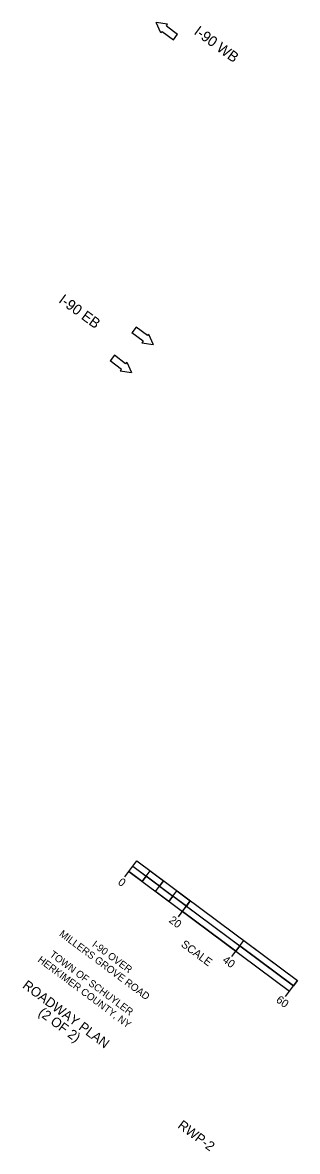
# Model space of a CAD drawing. Extents: x 337412 to 338044, y 1540627 to 1541298.
# Drawn here: x 337776.6 to 337858.9, y 1540627.3 to 1540965.9 of the extents above; entities that cross this region are included whole.
import ezdxf

# ---------------------------------------------------------------- set-up
doc = ezdxf.new("R2010")
doc.units = 0
for name, color, linetype in [('Default', 7, 'Continuous'), ('NSB_P', 7, 'Continuous'), ('NSB_P_T', 7, 'Continuous'), ('O_Details_Dimensions_Notes_P', 7, 'Continuous'), ('O_Details_Object Line 1_P', 7, 'Continuous')]:
    doc.layers.add(name, color=color, linetype=linetype)

msp = doc.modelspace()

# ---------------------------------------------------------------- linework, layer by layer
at = {"layer": 'NSB_P'}
for p, q in [((337807.22, 1540709.63), (337810.8, 1540714.45)), ((337810.8, 1540714.45), (337858.92, 1540678.61)), ((337808.41, 1540711.24), (337856.53, 1540675.4)), ((337809.6, 1540712.84), (337857.73, 1540677.01)), ((337812.42, 1540708.25), (337813.61, 1540709.85)), ((337816.43, 1540705.26), (337818.82, 1540708.47)), ((337820.44, 1540702.28), (337822.83, 1540705.49)), ((337823.26, 1540697.69), (337826.84, 1540702.5)), ((337839.3, 1540685.74), (337842.88, 1540690.55)), ((337855.34, 1540673.8), (337858.92, 1540678.61))]:
    msp.add_line(p, q, dxfattribs=at)
for points in [[(337809.6, 1540712.84), (337813.61, 1540709.85), (337812.42, 1540708.25), (337808.41, 1540711.24)], [(337814.81, 1540711.46), (337818.82, 1540708.47), (337817.62, 1540706.87), (337813.61, 1540709.85)], [(337817.62, 1540706.87), (337821.63, 1540703.88), (337820.44, 1540702.28), (337816.43, 1540705.26)], [(337822.83, 1540705.49), (337826.84, 1540702.5), (337825.65, 1540700.9), (337821.63, 1540703.88)], [(337825.65, 1540700.9), (337841.69, 1540688.95), (337840.49, 1540687.35), (337824.45, 1540699.29)], [(337842.88, 1540690.55), (337858.92, 1540678.61), (337857.73, 1540677.01), (337841.69, 1540688.95)]]:
    msp.add_lwpolyline(points, close=True, dxfattribs=at)
at = {"layer": 'O_Details_Object Line 1_P'}
for p, q in [((337820.03, 1540965.41), (337816.64, 1540965.89)), ((337818.04, 1540962.77), (337816.64, 1540965.89)), ((337819.66, 1540964.93), (337820.03, 1540965.41)), ((337819.66, 1540964.93), (337823.02, 1540962.4)), ((337818.04, 1540962.77), (337818.4, 1540963.25)), ((337818.4, 1540963.25), (337821.76, 1540960.72)), ((337821.76, 1540960.72), (337823.02, 1540962.4)), ((337810.62, 1540874.52), (337809.36, 1540872.84)), ((337813.98, 1540871.99), (337810.62, 1540874.52)), ((337812.72, 1540870.32), (337809.36, 1540872.84)), ((337812.72, 1540870.32), (337812.36, 1540869.84)), ((337812.36, 1540869.84), (337815.75, 1540869.35)), ((337814.34, 1540872.47), (337813.98, 1540871.99)), ((337814.34, 1540872.47), (337815.75, 1540869.35)), ((337804.08, 1540866.09), (337802.82, 1540864.41)), ((337806.18, 1540861.88), (337802.82, 1540864.41)), ((337807.44, 1540863.56), (337804.08, 1540866.09)), ((337807.8, 1540864.04), (337807.44, 1540863.56)), ((337807.8, 1540864.04), (337809.2, 1540860.92)), ((337806.18, 1540861.88), (337805.82, 1540861.4)), ((337805.82, 1540861.4), (337809.2, 1540860.92))]:
    msp.add_line(p, q, dxfattribs=at)

# ---------------------------------------------------------------- texts
at = {"layer": 'Default'}
for s, height, p in [('MILLERS GROVE ROAD', 2.16, (337787.39, 1540692.14)), ('I-90 OVER', 2.16, (337797.21, 1540688.99)), ('TOWN OF SCHUYLER', 2.16, (337784.52, 1540685.96)), ('HERKIMER COUNTY, NY', 2.16, (337780.93, 1540684.38)), ('ROADWAY PLAN', 2.88, (337776.33, 1540676.59)), ('(2 OF 2)', 2.88, (337781.07, 1540668.42)), ('RWP-2', 2.88, (337822.83, 1540634.61))]:
    msp.add_text(s, height=height, rotation=323.3259, dxfattribs=at).set_placement(p)
at = {"layer": 'NSB_P_T'}
for s, p in [('0', (337804.93, 1540707.62)), ('20', (337820.22, 1540696.24)), ('SCALE', (337823.83, 1540689)), ('40', (337836.26, 1540684.29)), ('60', (337852.32, 1540672.34))]:
    msp.add_text(s, height=2.4, rotation=323.3259, dxfattribs=at).set_placement(p)
at = {"layer": 'O_Details_Dimensions_Notes_P'}
for s, p in [('I-90 WB', (337827.69, 1540962.62)), ('I-90 EB', (337787.16, 1540882.13))]:
    msp.add_text(s, height=3.125, rotation=323.8105, dxfattribs=at).set_placement(p)

doc.saveas('drawing.dxf')
